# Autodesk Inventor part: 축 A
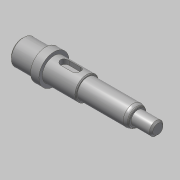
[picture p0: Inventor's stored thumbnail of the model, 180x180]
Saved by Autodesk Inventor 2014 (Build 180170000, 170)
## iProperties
Created: 2020-04
Part Number: 축 A
Material: 강철, 연강
Document SubType Name: Modeling
Designer: mduedu
Density: 7.86 g/cm^3
Appearance: Steel
Mass: 83.1595 g
Surface Area: 37.6208 cm^2
Volume: 10.5801 cm^3
Author: mduedu
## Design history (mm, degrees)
sketch "스케치1"
  geometry: L1 (0, 0)-(14, 0); L2 (14, 0)-(14, 7.5); L3 (14, 7.5)-(0, 7.5); L4 (0, 7.5)-(0, 0); L5 (14, 0)-(19, 0); L6 (19, 0)-(19, 9); L7 (19, 9)-(14, 9); L8 (14, 9)-(14, 0); L9 (19, 0)-(39, 0); L10 (39, 0)-(39, 7); L11 (39, 7)-(19, 7); L12 (19, 7)-(19, 0); L13 (39, 0)-(69, 0); L14 (69, 0)-(69, 6); L15 (69, 6)-(39, 6); L16 (39, 6)-(39, 0); L17 (69, 0)-(81, 0); L18 (81, 0)-(81, 4); L19 (81, 4)-(69, 4); L20 (69, 4)-(69, 0)
  constraints: 40 end point, 10 parallel, 5 horizontal, 5 perpendicular
  dimensions: "d0" = 81 distance between parallel lines of L18 L4; "d2" = 14 distance of L2.end L3.end; "d3" = 5 distance of L6.end L7.end; "d4" = 12 distance of L18.end L19.end; "d5" = 8 diameter of L19 L17; "d6" = 12 diameter of L15 L13; "d7" = 14 diameter of L11 L9; "d8" = 15 diameter of L3 L1; "d9" = 18 diameter of L7 L5; "d10" = 42 distance between parallel lines of L10 L18
revolve "회전1" sketch "스케치1" stored, may be unused: angle "d11" = 90 deg
sketch "스케치2"
  geometry: L1 (0, -7.5)-(0, 7.5) reference; L2 (0, 7.5)-(14, 7.5) reference; L3 (14, 7.5)-(14, 9) reference; L4 (14, 9)-(19, 9) reference; L5 (19, 9)-(19, 7) reference; L6 (19, 7)-(39, 7) reference; L7 (39, 7)-(39, 6) reference; L8 (39, 6)-(69, 6) reference; L9 (69, 6)-(69, 4) reference; L10 (69, 4)-(81, 4) reference; L11 (81, 4)-(81, -4) reference; L12 (81, -4)-(69, -4) reference; L13 (69, -4)-(69, -6) reference; L14 (69, -6)-(39, -6) reference; L15 (39, -6)-(39, -7) reference; L16 (39, -7)-(19, -7) reference; L17 (19, -7)-(19, -9) reference; L18 (19, -9)-(14, -9) reference; L19 (14, -9)-(14, -7.5) reference; L20 (14, -7.5)-(0, -7.5) reference; L21 (81, -4)-(73, -4); L22 (73, -4)-(73, -2.8); L23 (73, -2.8)-(81, -2.8); L24 (81, -2.8)-(81, -4); 1 further point
  constraints: 8 end point, 2 parallel, 1 horizontal, 1 perpendicular
  dimensions: "d12" = 8 distance of L22.end L23.end; "d13" = 1.2 distance of L21.end L22.end
extrude "돌출1" cut sketch "스케치2" stored distance "d14" = 2; taper "d15" = 0 deg
fillet "모깎기1" dims "d16" = 1
sketch "스케치3"
  geometry: L1 (0, -7.5)-(0, 7.5) reference; L2 (0, 7.5)-(14, 7.5) reference; L3 (14, 7.5)-(14, 9) reference; L4 (14, 9)-(19, 9) reference; L5 (19, 9)-(19, 7) reference; L6 (19, 7)-(39, 7) reference; L7 (39, 7)-(39, 6) reference; L8 (39, 6)-(69, 6) reference; L9 (69, 6)-(69, 4) reference; L10 (69, 4)-(81, 4) reference; L11 (81, 4)-(81, -2.8) reference; L12 (81, -2.8)-(73, -2.8) reference; L13 (73, -2.8)-(73, -4) reference; L14 (73, -4)-(69, -4) reference; L15 (69, -4)-(69, -6) reference; L16 (69, -6)-(39, -6) reference; L17 (39, -6)-(39, -7) reference; L18 (39, -7)-(19, -7) reference; L19 (19, -7)-(19, -9) reference; L20 (19, -9)-(14, -9) reference; L21 (14, -9)-(14, -7.5) reference; L22 (14, -7.5)-(0, -7.5) reference; L23 (23, 7)-(35, 7); L24 (35, 7)-(35, 4); L25 (35, 4)-(23, 4); L26 (23, 4)-(23, 7); 1 further point
  constraints: 8 end point, 2 parallel, 1 horizontal, 1 perpendicular, 1 point on line
  dimensions: "d17" = 12 distance of L24.end L25.end; "d18" = 3 distance of L23.end L24.end; "d19" = 4 distance from line of L26 L4.end
extrude "돌출2" cut sketch "스케치3" stored distance "d20" = 5; taper "d21" = 0 deg
fillet "모깎기2" dims "d22" = 2.5
chamfer "모따기1" distance "d23" = 1; stored, may be unused: second distance "d24" = 2, angle "d25" = 45 deg
chamfer "모따기2" distance "d26" = 0.5; stored, may be unused: second distance "d27" = 2, angle "d28" = 45 deg
fillet "모깎기3" dims "d29" = 0.3
chamfer "모따기3" distance "d30" = 1.56; stored, may be unused: second distance "d31" = 2, angle "d32" = 30 deg
fillet "모깎기4" dims "d33" = 4, "d34" = 0.5
node "솔리드1"
node "절단 모서리 투영1"
node "절단 모서리 투영2"
